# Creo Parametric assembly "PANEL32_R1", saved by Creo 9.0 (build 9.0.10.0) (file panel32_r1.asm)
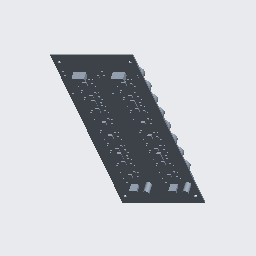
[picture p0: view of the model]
Units: millimeter Newton Second (mmNs); MM, TONNE, SECS

Created from: MMNS_ASM_DESIGN_ABS.ASM

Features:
  1. datum plane "ASM_RIGHT"
  2. datum plane "ASM_TOP"
  3. datum plane "ASM_FRONT"
  4. coordinate system
  5. coordinate system
  6. component "PCB32_R1"
  7. coordinate system
  8. component "C0805_R1"
  9. coordinate system
  10. component "C0805_R1"
  11. coordinate system
  12. component "C0805_R1"
  13. coordinate system
  14. component "C0805_R1"
  15. coordinate system
  16. component "C0805_R1"
  17. coordinate system
  18. component "C0805_R1"
  19. coordinate system
  20. component "C0805_R1"
  21. coordinate system
  22. component "C0805_R1"
  23. coordinate system
  24. component "C0805_R1"
  25. coordinate system
  26. component "C0805_R1"
  27. coordinate system
  28. component "CP63_R1"
  29. coordinate system
  30. component "C0805_R1"
  31. coordinate system
  32. component "C0805_R1"
  33. coordinate system
  34. component "C0805_R1"
  35. coordinate system
  36. component "C0805_R1"
  37. coordinate system
  38. component "C0805_R1"
  39. coordinate system
  40. component "C0805_R1"
  41. coordinate system
  42. component "C0805_R1"
  43. coordinate system
  44. component "C0805_R1"
  45. coordinate system
  46. component "C0805_R1"
  47. coordinate system
  48. component "C0805_R1"
  49. coordinate system
  50. component "C0805_R1"
  51. coordinate system
  52. component "C0805_R1"
  53. coordinate system
  54. component "C0805_R1"
  55. coordinate system
  56. component "C0805_R1"
  57. coordinate system
  58. component "C0805_R1"
  59. coordinate system
  60. component "C0805_R1"
  61. coordinate system
  62. component "C0805_R1"
  63. coordinate system
  64. component "C0805_R1"
  65. coordinate system
  66. component "C0805_R1"
  67. coordinate system
  68. component "C0805_R1"
  69. coordinate system
  70. component "C0805_R1"
  71. coordinate system
  72. component "CP63_R1"
  73. coordinate system
  74. component "C0805_R1"
  75. coordinate system
  76. component "C0805_R1"
  77. coordinate system
  78. component "C0805_R1"
  79. coordinate system
  80. component "C0805_R1"
  81. coordinate system
  82. component "C0805_R1"
  83. coordinate system
  84. component "C0805_R1"
  85. coordinate system
  86. component "C0805_R1"
  87. coordinate system
  88. component "HDR10_R1"
  89. coordinate system
  90. component "HDR10_R1"
  91. coordinate system
  92. component "HDR3_R1"
  93. coordinate system
  94. component "HDR3_R1"
  95. coordinate system
  96. component "SOT23_R1"
  97. coordinate system
  98. component "SOT23_R1"
  99. coordinate system
  100. component "R0805_R1"
  101. coordinate system
  102. component "R0805_R1"
  103. coordinate system
  104. component "R0805_R1"
  105. coordinate system
  106. component "R0805_R1"
  107. coordinate system
  108. component "R0805_R1"
  109. coordinate system
  110. component "R0805_R1"
  111. coordinate system
  112. component "R0805_R1"
  113. coordinate system
  114. component "R0805_R1"
  115. coordinate system
  116. component "R0805_R1"
  117. coordinate system
  118. component "R0805_R1"
  119. coordinate system
  120. component "R0805_R1"
  121. coordinate system
  122. component "R0805_R1"
  123. coordinate system
  124. component "R0805_R1"
  125. coordinate system
  126. component "R0805_R1"
  127. coordinate system
  128. component "R0805_R1"
  129. coordinate system
  130. component "R0805_R1"
  131. coordinate system
  132. component "R0805_R1"
  133. coordinate system
  134. component "R0805_R1"
  135. coordinate system
  136. component "R0805_R1"
  137. coordinate system
  138. component "R0805_R1"
  139. coordinate system
  140. component "R0805_R1"
  141. coordinate system
  142. component "R0805_R1"
  143. coordinate system
  144. component "R0805_R1"
  145. coordinate system
  146. component "R0805_R1"
  147. coordinate system
  148. component "R0805_R1"
  149. coordinate system
  150. component "R0805_R1"
  151. coordinate system
  152. component "R0805_R1"
  153. coordinate system
  154. component "R0805_R1"
  155. coordinate system
  156. component "R0805_R1"
  157. coordinate system
  158. component "R0805_R1"
  159. coordinate system
  160. component "R0805_R1"
  161. coordinate system
  162. component "R0805_R1"
  163. coordinate system
  164. component "R0805_R1"
  165. coordinate system
  166. component "R0805_R1"
  167. coordinate system
  168. component "R0805_R1"
  169. coordinate system
  170. component "R0805_R1"
  171. coordinate system
  172. component "R0805_R1"
  173. coordinate system
  174. component "R0805_R1"
  175. coordinate system
  176. component "R0805_R1"
  177. coordinate system
  178. component "R0805_R1"
  179. coordinate system
  180. component "R0805_R1"
  181. coordinate system
  182. component "R0805_R1"
  183. coordinate system
  184. component "R0805_R1"
  185. coordinate system
  186. component "R0805_R1"
  187. coordinate system
  188. component "R0805_R1"
  189. coordinate system
  190. component "R0805_R1"
  191. coordinate system
  192. component "R0805_R1"
  193. coordinate system
  194. component "R0805_R1"
  195. coordinate system
  196. component "R0805_R1"
  197. coordinate system
  198. component "R0805_R1"
  199. coordinate system
  200. component "TX16_R1"
  201. coordinate system
  202. component "TX16_R1"
  203. coordinate system
  204. component "TX16_R1"
  205. coordinate system
  206. component "TX16_R1"
  207. coordinate system
  208. component "TX16_R1"
  209. coordinate system
  210. component "TX16_R1"
  211. coordinate system
  212. component "TX16_R1"
  213. coordinate system
  214. component "TX16_R1"
  215. coordinate system
  216. component "TX16_R1"
  217. coordinate system
  218. component "TX16_R1"
  219. coordinate system
  220. component "TX16_R1"
  221. coordinate system
  222. component "TX16_R1"
  223. coordinate system
  224. component "TX16_R1"
  225. coordinate system
  226. component "TX16_R1"
  227. coordinate system
  228. component "TX16_R1"
  229. coordinate system
  230. component "TX16_R1"
  231. coordinate system
  232. component "TX16_R1"
  233. coordinate system
  234. component "TX16_R1"
  235. coordinate system
  236. component "TX16_R1"
  237. coordinate system
  238. component "TX16_R1"
  239. coordinate system
  240. component "TX16_R1"
  241. coordinate system
  242. component "TX16_R1"
  243. coordinate system
  244. component "TX16_R1"
  245. coordinate system
  246. component "TX16_R1"
  247. coordinate system
  248. component "TX16_R1"
  249. coordinate system
  250. component "TX16_R1"
  251. coordinate system
  252. component "TX16_R1"
  253. coordinate system
  254. component "TX16_R1"
  255. coordinate system
  256. component "TX16_R1"
  257. coordinate system
  258. component "TX16_R1"
  259. coordinate system
  260. component "TX16_R1"
  261. coordinate system
  262. component "TX16_R1"
  263. coordinate system
  264. component "SO16_R1"
  265. coordinate system
  266. component "SO8_R1"
  267. coordinate system
  268. component "SO8_R1"
  269. coordinate system
  270. component "SO8_R1"
  271. coordinate system
  272. component "SO8_R1"
  273. coordinate system
  274. component "SO8_R1"
  275. coordinate system
  276. component "SO8_R1"
  277. coordinate system
  278. component "SO8_R1"
  279. coordinate system
  280. component "SO8_R1"
  281. coordinate system
  282. component "SO8_R1"
  283. coordinate system
  284. component "SO8_R1"
  285. coordinate system
  286. component "SO16_R1"
  287. coordinate system
  288. component "SO8_R1"
  289. coordinate system
  290. component "SO16_R1"
  291. coordinate system
  292. component "SO16_R1"
  293. coordinate system
  294. component "SO8_R1"
  295. coordinate system
  296. component "SO8_R1"
  297. coordinate system
  298. component "SO8_R1"
  299. coordinate system
  300. component "SO8_R1"
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
Other named items: ACS0, ACS1, ACS2, ACS3, ACS4, ACS5, ACS6, ACS7, ACS8, ACS9, ACS10, ACS11, ACS12, ACS13, ACS14, ACS15, ACS16, ACS17, ACS18, ACS19, ACS20, ACS21, ACS22, ACS23, ACS24, ACS25, ACS26, ACS27, ACS28, ACS29, ACS30, ACS31, ACS32, ACS33, ACS34, ACS35, ACS36, ACS37, ACS38, ACS39, ACS40, ACS41, ACS42, ACS43, ACS44, ACS45, ACS46, ACS47, ACS48, ACS49, ACS50, ACS51, ACS52, ACS53, ACS54, ACS55, ACS56, ACS57, ACS58, ACS59, ACS60, ACS61, ACS62, ACS63, ACS64, ACS65, ACS66, ACS67, ACS68, ACS69, ACS70, ACS71, ACS72, ACS73, ACS74, ACS75, ACS76, ACS77, ACS78, ACS79, ACS80, ACS81, ACS82, ACS83, ACS84, ACS85, ACS86, ACS87, ACS88, ACS89, ACS90, ACS91, ACS92, ACS93, ACS94, ACS95, ACS96, ACS97, ACS98, ACS99, ACS100, ACS101, ACS102, ACS103, ACS104, ACS105, ACS106, ACS107, ACS108, ACS109, ACS110, ACS111, ACS112, ACS113, ACS114, ACS115, ACS116, ACS117, ACS118, ACS119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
